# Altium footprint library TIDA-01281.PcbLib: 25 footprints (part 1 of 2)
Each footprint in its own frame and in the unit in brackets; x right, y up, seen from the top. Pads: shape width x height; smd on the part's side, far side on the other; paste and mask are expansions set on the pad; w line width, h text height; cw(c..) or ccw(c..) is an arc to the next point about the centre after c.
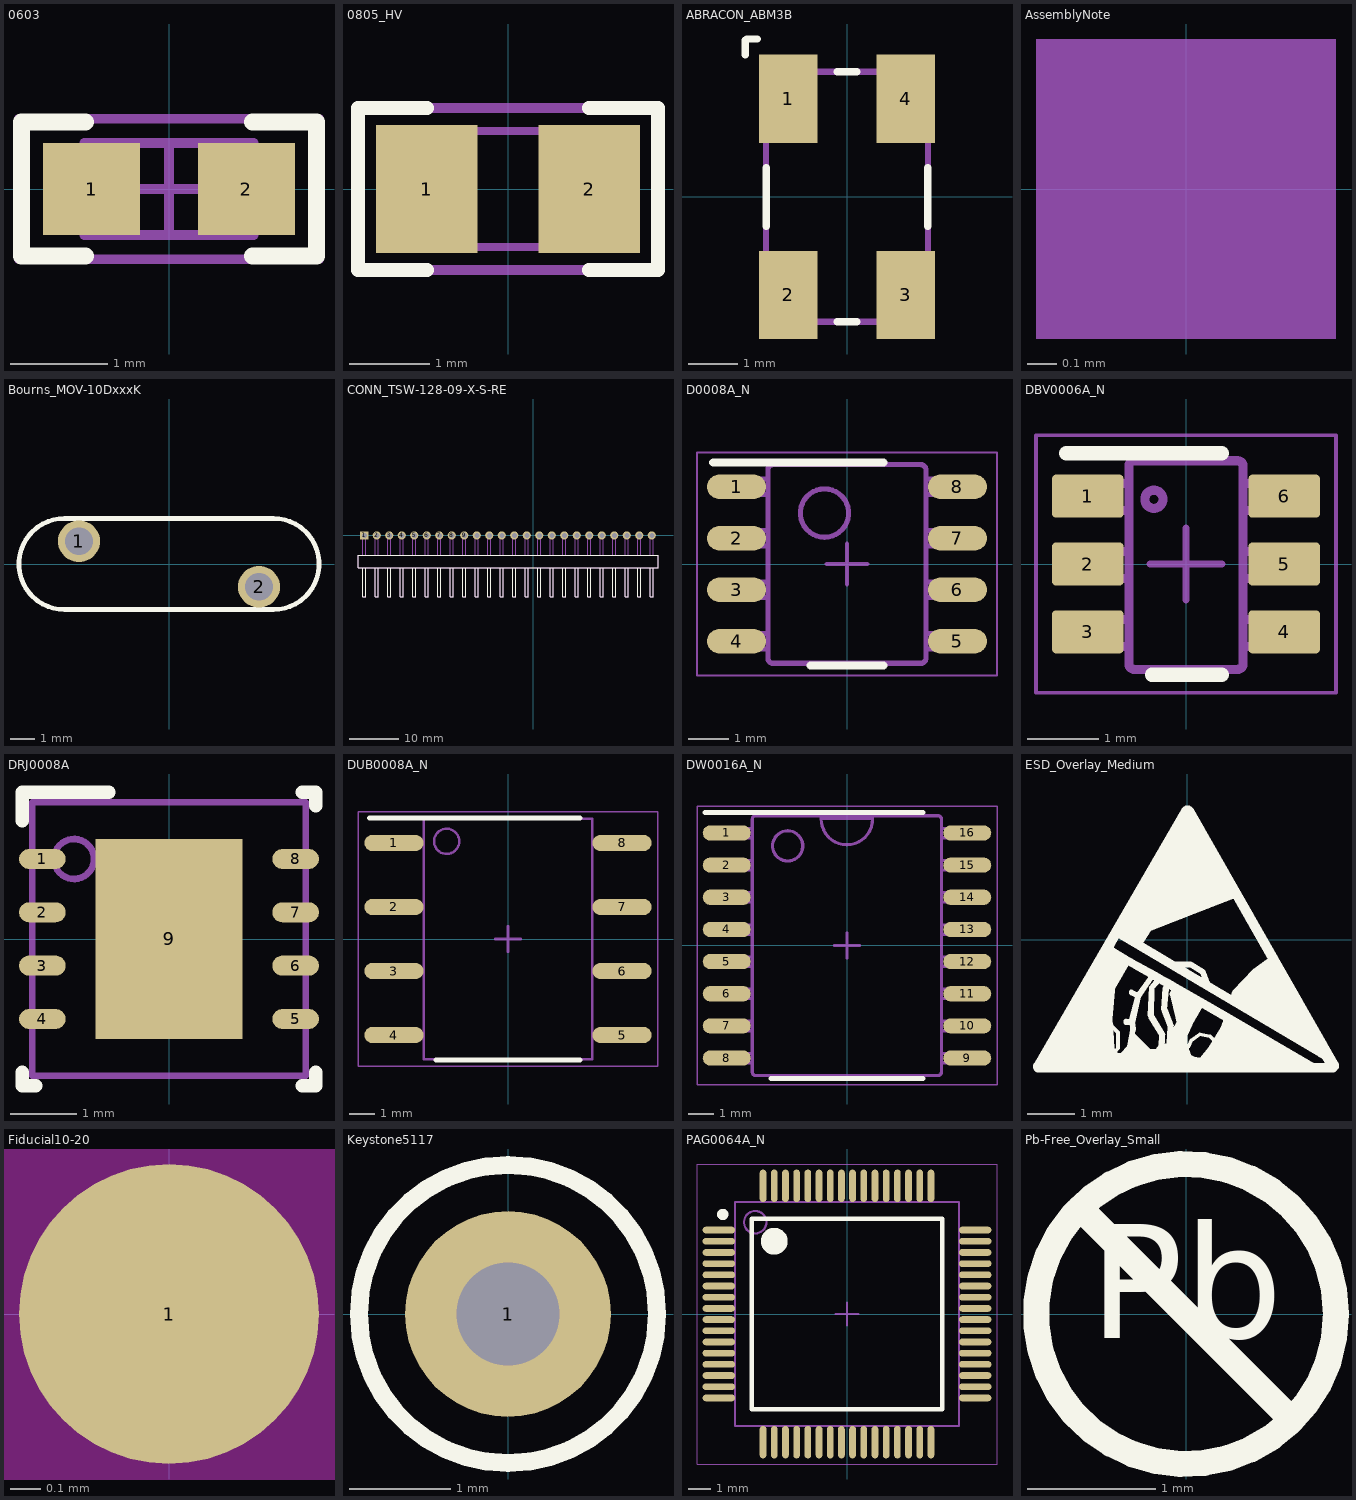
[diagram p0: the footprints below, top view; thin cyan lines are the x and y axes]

## 0603 [mm] "0603 from SM-752 data"
height 1
pads (2):
  rect 1x0.95 smd: 1(-0.8,0) 2(0.8,0)
Top Overlay:
  lines w0.178: -0.864,-0.691 -1.524,-0.691 -1.524,0.693 -0.864,0.693 ; 0.864,-0.691 1.524,-0.691 1.524,0.693 0.864,0.693
Mechanical 5:
  lines w0.1: -1.55,-0.725 -1.55,0.725 1.55,0.725 1.55,-0.725 -1.55,-0.725
  text ".Designator" at 0.94,0.381 h0.76
Mechanical 13:
  lines w0.1: -0.55,-0.475 -0.55,0.475 ; 0.55,-0.475 0.55,0.475 ; -0.875,-0.475 0.875,-0.475 0.875,0.475 -0.875,0.475 -0.875,-0.475
Mechanical 15:
  lines w0.1: -0.475,0 0.475,0 ; 0,-0.475 0,0.475 ; -1.55,-0.725 1.55,-0.725 1.55,0.725 -1.55,0.725 -1.55,-0.725
3D body: height 1, standoff 0, extent -0.874,-0.474 -0.551,0.474
3D body: height 1, standoff 0, extent -0.549,-0.474 0.549,0.474
3D body: height 1, standoff 0, extent 0.551,-0.474 0.874,0.474

## 0805_HV [mil] "0805 with 30mil clearance between pads"
height 57.09
pads (2):
  rect 50x63 smd: 1(-40,0) 2(40,0)
Top Overlay:
  lines w7: -40,-40 -74,-40 -74,0 -74,40 -40,40 ; 40,-40 74,-40 74,0 74,40 40,40
Mechanical 5:
  lines w5: -74,-40 74,-40 74,40 -74,40 -74,-40
  text ".Designator" at -47,-17 h30
Mechanical 13:
  lines w3.94: -25.59,-28.54 -25.59,28.54 ; 25.59,-28.54 25.59,28.54 ; -43.31,-28.54 43.31,-28.54 43.31,28.54 -43.31,28.54 -43.31,-28.54
3D body: height 57.09, standoff 0, extent -43.29,-28.52 -25.61,28.52
3D body: height 57.09, standoff 0, extent -25.57,-28.52 25.57,28.52
3D body: height 57.09, standoff 0, extent 25.61,-28.52 43.29,28.52

## ABRACON_ABM3B [mm] "ABRACON"
height 1.1
pads (4):
  rect 1.2x1.8 smd: 1(-1.2,2) 2(-1.2,-2) 3(1.2,-2) 4(1.2,2)
Top Overlay:
  lines w0.15: -2.075,2.9 -2.075,3.2 ; -2.05,3.22 -1.825,3.22 ; -1.65,-0.6 -1.65,0.6 ; -0.2,-2.55 0.2,-2.55 ; -0.2,2.55 0.2,2.55 ; 1.65,-0.6 1.65,0.6
Mechanical 5:
  circle w0.1: c-1.151,2 r0.251
  lines w0.127: -1.65,-2.55 -1.65,2.55 1.65,2.55 1.65,-2.55 -1.65,-2.55
  text ".Designator" at 0.381,0.381 h0.76
3D body: height 1.1, standoff 0, extent -1.649,-2.549 1.649,2.549
3D body: height 1.12, standoff 1, extent -1.456,1.744 -0.944,2.256

## AssemblyNote [mm] "Assembly Note"
Mechanical 5:
  rectangle: -0.508,-0.508 0.508,0.508
  text ".Designator" at -4.191,-0.508 h1.02
  text ".Comment" at 1.143,-0.508 h1.02

## Bourns_MOV-10DxxxK [mm] "Bourns"
height 15.5
pads (2):
  round 1.75 hole 1.15: 1(-3.75,0.95) 2(3.75,-0.95)
Top Overlay:
  lines w0.2: -4.35,-1.9 cw(c-4.35,0) -4.35,1.9 4.35,1.9 cw(c4.35,0) 4.35,-1.9 -4.35,-1.9
Mechanical 5:
  lines w0.1: -4.35,-1.9 cw(c-4.35,0) -4.35,1.9 4.35,1.9 cw(c4.35,0) 4.35,-1.9 -4.35,-1.9
  text ".Designator" at -1.85,-0.55 h0.76
3D body: height 15.49, standoff 3.01, extent -6.225,-1.9 6.225,1.9
3D body: height 5, standoff -4, extent -4.196,0.501 -3.3,1.399
3D body: height 5, standoff -4, extent 3.304,-1.399 4.2,-0.501

## CONN_TSW-128-09-X-S-RE [mm] "Samtec 100mil, 1x28, Extended Right-angle"
height 2.54
pads (24):
  rect 1.65x1.65 hole 1.016 mask+0.064: 1(-34.29,0)
  round 1.65 hole 1.016 mask+0.064: 2(-31.75,0) 3(-29.21,0) 4(-26.67,0) 5(-24.13,0) 6(-21.59,0) 7(-19.05,0) 8(-16.51,0) 9(-13.97,0) 10(-11.43,0) 11(-8.89,0) 12(-6.35,0) 13(-3.81,0) 14(-1.27,0) 15(1.27,0) 16(3.81,0) 17(6.35,0) 18(8.89,0) 19(11.43,0) 20(13.97,0) 21(16.51,0) 22(19.05,0) 23(21.59,0) 24(24.13,0)
Top Overlay:
  lines w0.178: -34.608,-6.604 -34.608,-12.446 -33.972,-12.446 -33.972,-6.604 ; -32.067,-6.604 -32.067,-12.446 -31.432,-12.446 -31.432,-6.604 ; -29.527,-6.604 -29.527,-12.446 -28.892,-12.446 -28.892,-6.604 ; -26.987,-6.604 -26.987,-12.446 -26.352,-12.446 -26.352,-6.604 ; -24.447,-6.604 -24.447,-12.446 -23.812,-12.446 -23.812,-6.604 ; -21.907,-6.604 -21.907,-12.446 -21.273,-12.446 -21.273,-6.604 ; -19.367,-6.604 -19.367,-12.446 -18.732,-12.446 -18.732,-6.604 ; -16.828,-6.604 -16.828,-12.446 -16.192,-12.446 -16.192,-6.604 ; -14.287,-6.604 -14.287,-12.446 -13.652,-12.446 -13.652,-6.604 ; -11.747,-6.604 -11.747,-12.446 -11.112,-12.446 -11.112,-6.604 ; -9.207,-6.604 -9.207,-12.446 -8.572,-12.446 -8.572,-6.604 ; -6.667,-6.604 -6.667,-12.446 -6.032,-12.446 -6.032,-6.604 ; -4.127,-6.604 -4.127,-12.446 -3.492,-12.446 -3.492,-6.604 ; -1.587,-6.604 -1.587,-12.446 -0.953,-12.446 -0.953,-6.604 ; 0.953,-6.604 0.953,-12.446 1.587,-12.446 1.587,-6.604 ; 3.492,-6.604 3.492,-12.446 4.127,-12.446 4.127,-6.604 ; 6.032,-6.604 6.032,-12.446 6.667,-12.446 6.667,-6.604 ; 8.572,-6.604 8.572,-12.446 9.207,-12.446 9.207,-6.604 ; 11.112,-6.604 11.112,-12.446 11.747,-12.446 11.747,-6.604 ; 13.652,-6.604 13.652,-12.446 14.287,-12.446 14.287,-6.604 ; 16.192,-6.604 16.192,-12.446 16.828,-12.446 16.828,-6.604 ; 18.732,-6.604 18.732,-12.446 19.367,-12.446 19.367,-6.604 ; 21.273,-6.604 21.273,-12.446 21.907,-12.446 21.907,-6.604 ; 23.812,-6.604 23.812,-12.446 24.447,-12.446 24.447,-6.604 ; -35.56,-6.604 -33.02,-6.604 -30.48,-6.604 -27.94,-6.604 -25.4,-6.604 -22.86,-6.604 -20.32,-6.604 -17.78,-6.604 -15.24,-6.604 -12.7,-6.604 -10.16,-6.604 -7.62,-6.604 -5.08,-6.604 -2.54,-6.604 0,-6.604 2.54,-6.604 5.08,-6.604 7.62,-6.604 10.16,-6.604 12.7,-6.604 15.24,-6.604 17.78,-6.604 20.32,-6.604 22.86,-6.604 25.4,-6.604 25.4,-4.064 22.86,-4.064 20.32,-4.064 17.78,-4.064 15.24,-4.064 12.7,-4.064 10.16,-4.064 7.62,-4.064 5.08,-4.064 2.54,-4.064 0,-4.064 -2.54,-4.064 -5.08,-4.064 -7.62,-4.064 -10.16,-4.064 -12.7,-4.064 -15.24,-4.064 -17.78,-4.064 -20.32,-4.064 -22.86,-4.064 -25.4,-4.064 -27.94,-4.064 -30.48,-4.064 -33.02,-4.064 -35.56,-4.064 -35.56,-6.604
Mechanical 5:
  drawing of 242 lines, arcs and shapes, not listed
  text ".Designator" at -6.35,-5.588 h0.76

## D0008A_N [mm] "SOIC, 8-Leads, Body 4.9x3.9mm, Pitch 1.27mm, IPC Medium Density"
height 1.75
pads (8):
  oval 1.45x0.6 smd: 1(-2.725,1.905) 2(-2.725,0.635) 3(-2.725,-0.635) 4(-2.725,-1.905) 5(2.725,-1.905) 6(2.725,-0.635) 7(2.725,0.635) 8(2.725,1.905)
Top Overlay:
  lines w0.2: -3.3,2.5 0.9,2.5 ; -0.9,-2.5 0.9,-2.5
Mechanical 5:
  lines w0.127: -2.375,-2.095 -2.375,-1.715 ; -2.375,-2.095 -2.589,-2.095 -3.002,-2.095 -3.002,-1.715 -2.589,-1.715 -2.375,-1.715 ; -2.375,-2.095 -1.995,-2.095 -1.952,-2.095 -1.952,-1.715 -1.995,-1.715 -2.375,-1.715 ; -2.375,-0.825 -2.375,-0.445 ; -2.375,-0.825 -2.589,-0.825 -3.002,-0.825 -3.002,-0.445 -2.589,-0.445 -2.375,-0.445 ; -2.375,-0.825 -1.995,-0.825 -1.952,-0.825 -1.952,-0.445 -1.995,-0.445 -2.375,-0.445 ; -2.375,0.445 -2.375,0.825 ; -2.375,0.445 -2.589,0.445 -3.002,0.445 -3.002,0.825 -2.589,0.825 -2.375,0.825 ; -2.375,0.445 -1.995,0.445 -1.952,0.445 -1.952,0.825 -1.995,0.825 -2.375,0.825 ; -2.375,1.715 -2.375,2.095 ; -2.375,1.715 -2.589,1.715 -3.002,1.715 -3.002,2.095 -2.589,2.095 -2.375,2.095 ; -2.375,1.715 -1.995,1.715 -1.952,1.715 -1.952,2.095 -1.995,2.095 -2.375,2.095 ; -0.332,-2.45 -0.182,-2.45 ; -0.332,-2.45 -0.182,-2.45 ; -0.332,-2.45 -1.825,-2.45 -1.826,-2.45 cw(c-1.825,-2.323) -1.952,-2.324 -1.952,-2.323 -1.952,2.323 -1.952,2.324 cw(c-1.825,2.323) -1.826,2.45 -1.825,2.45 -0.332,2.45 ; -0.332,2.45 -0.182,2.45 ; -0.332,2.45 -0.182,2.45 ; -0.182,-2.45 0.178,-2.45 ; -0.182,2.45 0.178,2.45 ; 0.178,-2.45 0.328,-2.45 ; 0.178,-2.45 0.328,-2.45 ; 0.178,2.45 0.328,2.45 ; 0.178,2.45 0.328,2.45 ; 0.328,-2.45 1.821,-2.45 1.822,-2.45 ccw(c1.821,-2.323) 1.948,-2.324 1.948,-2.323 1.948,2.323 1.948,2.324 ccw(c1.821,2.323) 1.822,2.45 1.821,2.45 0.328,2.45 ; 2.371,-2.095 2.371,-1.715 ; 2.371,-2.095 1.991,-2.095 1.948,-2.095 1.948,-1.715 1.991,-1.715 2.371,-1.715 ; 2.371,-2.095 2.585,-2.095 2.998,-2.095 2.998,-1.715 2.585,-1.715 2.371,-1.715 ; 2.371,-0.825 2.371,-0.445 ; 2.371,-0.825 1.991,-0.825 1.948,-0.825 1.948,-0.445 1.991,-0.445 2.371,-0.445 ; 2.371,-0.825 2.585,-0.825 2.998,-0.825 2.998,-0.445 2.585,-0.445 2.371,-0.445 ; 2.371,0.445 2.371,0.825 ; 2.371,0.445 1.991,0.445 1.948,0.445 1.948,0.825 1.991,0.825 2.371,0.825 ; 2.371,0.445 2.585,0.445 2.998,0.445 2.998,0.825 2.585,0.825 2.371,0.825 ; 2.371,1.715 2.371,2.095 ; 2.371,1.715 1.991,1.715 1.948,1.715 1.948,2.095 1.991,2.095 2.371,2.095 ; 2.371,1.715 2.585,1.715 2.998,1.715 2.998,2.095 2.585,2.095 2.371,2.095 ; -0.555,0.659 ccw(c-0.555,1.256) -0.555,1.853 ccw(c-0.555,1.256) -0.555,0.659
  text ".Designator" at -0.254,0 h0.76
Mechanical 15:
  lines w0.05: -3.7,-2.75 -3.7,2.75 3.7,2.75 3.7,-2.75 -3.7,-2.75
  lines w0.1: -0.5,0 0.5,0 ; 0,-0.5 0,0.5
3D body: height 1.63, standoff 0, extent -3,-2.45 3,2.45

## DBV0006A_N [mm] "SOT23, 6-Leads, Body 2.9x1.6mm, Pitch 0.95mm, Lead Span 2.8mm, IPC Medium Density"
height 1.45
pads (6):
  rrect17% 1x0.6 smd: 1(-1.375,0.95) 2(-1.375,0) 3(-1.375,-0.95) 4(1.375,-0.95) 5(1.375,0) 6(1.375,0.95)
Top Overlay:
  lines w0.2: -1.675,1.55 0.5,1.55 ; -0.475,-1.55 0.5,-1.55
Mechanical 5:
  lines w0.127: 0.724,-1.475 ccw(c0.723,-1.399) 0.8,-1.399 0.8,1.37 ccw(c0.723,1.37) 0.724,1.446 ; 0.723,-1.475 0.724,-1.475 ; 0.723,-1.475 -0.724,-1.475 -0.725,-1.475 cw(c-0.724,-1.399) -0.801,-1.399 -0.801,1.37 cw(c-0.724,1.37) -0.725,1.446 -0.724,1.446 0.723,1.446 ; 0.723,1.446 0.724,1.446 ; -1.423,-1.154 -1.206,-1.154 -1.113,-1.154 -1.081,-1.154 -0.828,-1.154 -0.801,-1.154 -0.801,-0.78 -0.828,-0.78 -1.081,-0.78 -1.113,-0.78 -1.206,-0.78 -1.423,-0.78 -1.423,-1.154 ; -1.423,-0.202 -1.206,-0.202 -1.113,-0.202 -1.081,-0.202 -0.828,-0.202 -0.801,-0.202 -0.801,0.173 -0.828,0.173 -1.081,0.173 -1.113,0.173 -1.206,0.173 -1.423,0.173 -1.423,-0.202 ; -1.423,0.751 -1.206,0.751 -1.113,0.751 -1.081,0.751 -0.828,0.751 -0.801,0.751 -0.801,1.125 -0.828,1.125 -1.081,1.125 -1.113,1.125 -1.206,1.125 -1.423,1.125 -1.423,0.751 ; -0.577,0.906 cw(c-0.45,0.906) -0.323,0.906 cw(c-0.45,0.906) -0.577,0.906 ; 0.8,-1.154 0.827,-1.154 1.08,-1.154 1.112,-1.154 1.205,-1.154 1.422,-1.154 1.422,-0.78 1.205,-0.78 1.112,-0.78 1.08,-0.78 0.827,-0.78 0.8,-0.78 0.8,-1.154 ; 0.8,-0.202 0.827,-0.202 1.08,-0.202 1.112,-0.202 1.205,-0.202 1.422,-0.202 1.422,0.173 1.205,0.173 1.112,0.173 1.08,0.173 0.827,0.173 0.8,0.173 0.8,-0.202 ; 0.8,0.751 0.827,0.751 1.08,0.751 1.112,0.751 1.205,0.751 1.422,0.751 1.422,1.125 1.205,1.125 1.112,1.125 1.08,1.125 0.827,1.125 0.8,1.125 0.8,0.751
  text ".Designator" at 0.381,-1.016 h0.76
Mechanical 15:
  lines w0.05: -2.1,-1.8 2.1,-1.8 2.1,1.8 -2.1,1.8 -2.1,-1.8
  lines w0.1: -0.5,0 0.5,0 ; 0,-0.5 0,0.5
3D body: height 1.12, standoff 0, extent -1.422,-1.461 1.423,1.46

## DRJ0008A [mm] "SON, 8-Leads, Body 4x4mm, Pitch 0.8mm, Thermal Pad 3x2.2mm, TI Recommended"
height 0.8
pads (9):
  oval 0.7x0.3 smd: 1(-1.9,1.2) 2(-1.9,0.4) 3(-1.9,-0.4) 4(-1.9,-1.2) 5(1.9,-1.2) 6(1.9,-0.4) 7(1.9,0.4) 8(1.9,1.2)
  rect 2.2x3 smd paste-1.1: 9(0,0)
Top Overlay:
  lines w0.2: -2.2,-2 -2.2,-2.2 -2,-2.2 ; -2.2,1.775 -2.2,2.2 -0.9,2.2 ; 2,-2.2 2.2,-2.2 2.2,-2 ; 2,2.2 2.2,2.2 2.2,2
Top Paste:
  rectangle: 0.1,0.1 1.081,1.41
  region: -0.1,1.41 -1.081,1.41 -1.081,0.1 -0.1,0.1
  region: -0.1,-0.1 -1.081,-0.1 -1.081,-1.41 -0.1,-1.41
  rectangle: 0.1,-1.41 1.081,-0.1
Mechanical 5:
  circle w0.1: c-1.425,1.2 r0.3
  lines w0.1: -2.05,-2.05 2.05,-2.05 2.05,2.05 -2.05,2.05 -2.05,-2.05
  text ".Designator" at -0.305,0.508 h0.76
3D body: height 0.8, standoff 0, extent -2.05,-2.05 2.05,2.05
3D body: height 0.81, standoff 0.5, extent -1.73,0.895 -1.12,1.505

## DUB0008A_N [mm] "SOP, 8-Leads, Body 9.5x6.62mm, Pitch 2.54mm, IPC Medium Density"
height 4.85
pads (8):
  oval 2.35x0.65 smd: 1(-4.525,3.81) 2(-4.525,1.27) 3(-4.525,-1.27) 4(-4.525,-3.81) 5(4.525,-3.81) 6(4.525,-1.27) 7(4.525,1.27) 8(4.525,3.81)
Top Overlay:
  lines w0.2: -5.5,4.8 2.85,4.8 ; -2.85,-4.8 2.85,-4.8
Mechanical 5:
  circle w0.1: c-2.435,3.875 r0.5
  lines w0.1: -3.335,-4.775 3.335,-4.775 3.335,4.775 -3.335,4.775 -3.335,-4.775
  text ".Designator" at -0.533,0.838 h0.76
Mechanical 15:
  lines w0.05: -5.95,-5.05 -5.95,5.05 5.95,5.05 5.95,-5.05 -5.95,-5.05
  lines w0.1: -0.5,0 0.5,0 ; 0,-0.5 0,0.5
3D body: height 4.85, standoff 0, extent -5.214,-4.75 5.215,4.75

## DW0016A_N [mm] "SOIC, 16-Leads, Body 10.3x7.5mm, Pitch 1.27mm, IPC Medium Density"
height 2.64
pads (16):
  oval 1.9x0.6 smd: 1(-4.75,4.445) 2(-4.75,3.175) 3(-4.75,1.905) 4(-4.75,0.635) 5(-4.75,-0.635) 6(-4.75,-1.905) 7(-4.75,-3.175) 8(-4.75,-4.445) 9(4.75,-4.445) 10(4.75,-3.175) 11(4.75,-1.905) 12(4.75,-0.635) 13(4.75,0.635) 14(4.75,1.905) 15(4.75,3.175) 16(4.75,4.445)
Top Overlay:
  lines w0.2: -5.6,5.25 3,5.25 ; -3,-5.25 3,-5.25
Mechanical 5:
  drawing of 193 lines, arcs and shapes, not listed
  text ".Designator" at -0.548,0.633 h0.76
Mechanical 15:
  lines w0.05: -5.925,-5.5 -5.925,5.5 5.925,5.5 5.925,-5.5 -5.925,-5.5
  lines w0.1: -0.5,0 0.5,0 ; 0,-0.5 0,0.5
3D body: height 2.54, standoff 0, extent -5.143,-5.131 5.144,5.131

## ESD_Overlay_Medium [mm]
Top Overlay:
  drawing of 6916 lines, arcs and shapes, not listed

## Fiducial10-20 [mm]
height 28.5
pads (1):
  round 1 smd mask+0.5: 1(0,0)
Top Layer keep-out:
  circle w1.178: c0,0 r0.5

## Keystone5117 [mil] "For Keystone 500x miniature loop terminals"
height 181.1
pads (1):
  round 80 hole 40: 1(0,0)
Top Overlay:
  circle w7: c0,0 r58
Mechanical 5:
  circle w5: c0,0 r58.31
  text ".Designator" at -35,-13 h30
3D body: height 181.97, standoff -118.11, extent -49.03,-49.23 49,49

## PAG0064A_N [mm] "Thin QFP, 64-Leads, Body 10x10mm, Pitch 0.5mm, IPC Medium Density"
height 1.2
pads (64):
  oval 1.45x0.3 smd: 1(-5.725,3.75) 2(-5.725,3.25) 3(-5.725,2.75) 4(-5.725,2.25) 5(-5.725,1.75) 6(-5.725,1.25) 7(-5.725,0.75) 8(-5.725,0.25) 9(-5.725,-0.25) 10(-5.725,-0.75) 11(-5.725,-1.25) 12(-5.725,-1.75) 13(-5.725,-2.25) 14(-5.725,-2.75) 15(-5.725,-3.25) 16(-5.725,-3.75) 33(5.725,-3.75) 34(5.725,-3.25) 35(5.725,-2.75) 36(5.725,-2.25) 37(5.725,-1.75) 38(5.725,-1.25) 39(5.725,-0.75) 40(5.725,-0.25) 41(5.725,0.25) 42(5.725,0.75) 43(5.725,1.25) 44(5.725,1.75) 45(5.725,2.25) 46(5.725,2.75) 47(5.725,3.25) 48(5.725,3.75)
  oval 0.3x1.45 smd: 17(-3.75,-5.725) 18(-3.25,-5.725) 19(-2.75,-5.725) 20(-2.25,-5.725) 21(-1.75,-5.725) 22(-1.25,-5.725) 23(-0.75,-5.725) 24(-0.25,-5.725) 25(0.25,-5.725) 26(0.75,-5.725) 27(1.25,-5.725) 28(1.75,-5.725) 29(2.25,-5.725) 30(2.75,-5.725) 31(3.25,-5.725) 32(3.75,-5.725) 49(3.75,5.725) 50(3.25,5.725) 51(2.75,5.725) 52(2.25,5.725) 53(1.75,5.725) 54(1.25,5.725) 55(0.75,5.725) 56(0.25,5.725) 57(-0.25,5.725) 58(-0.75,5.725) 59(-1.25,5.725) 60(-1.75,5.725) 61(-2.25,5.725) 62(-2.75,5.725) 63(-3.25,5.725) 64(-3.75,5.725)
Top Overlay:
  circle w0.6: c-3.25,3.25 r0.3
  circle w0.25: c-5.55,4.45 r0.125
  lines w0.2: -4.25,-4.25 4.25,-4.25 4.25,4.25 -4.25,4.25 -4.25,-4.25
Mechanical 5:
  circle w0.1: c-4.1,4.1 r0.5
  lines w0.1: -5,-5 5,-5 5,5 -5,5 -5,-5
  text ".Designator" at 0.635,0.254 h0.76
Mechanical 15:
  lines w0.05: -6.7,-6.7 6.7,-6.7 6.7,6.7 -6.7,6.7 -6.7,-6.7
  lines w0.1: -0.5,0 0.5,0 ; 0,-0.5 0,0.5
3D body: height 1.09, standoff 0, extent -6,-6 6,6

## Pb-Free_Overlay_Small [mm]
Top Overlay:
  circle w0.203: c0,0 r1.168
  lines w0.203: -0.826,0.826 0.826,-0.826
  text "Pb" at -0.752,-0.48 h1.52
